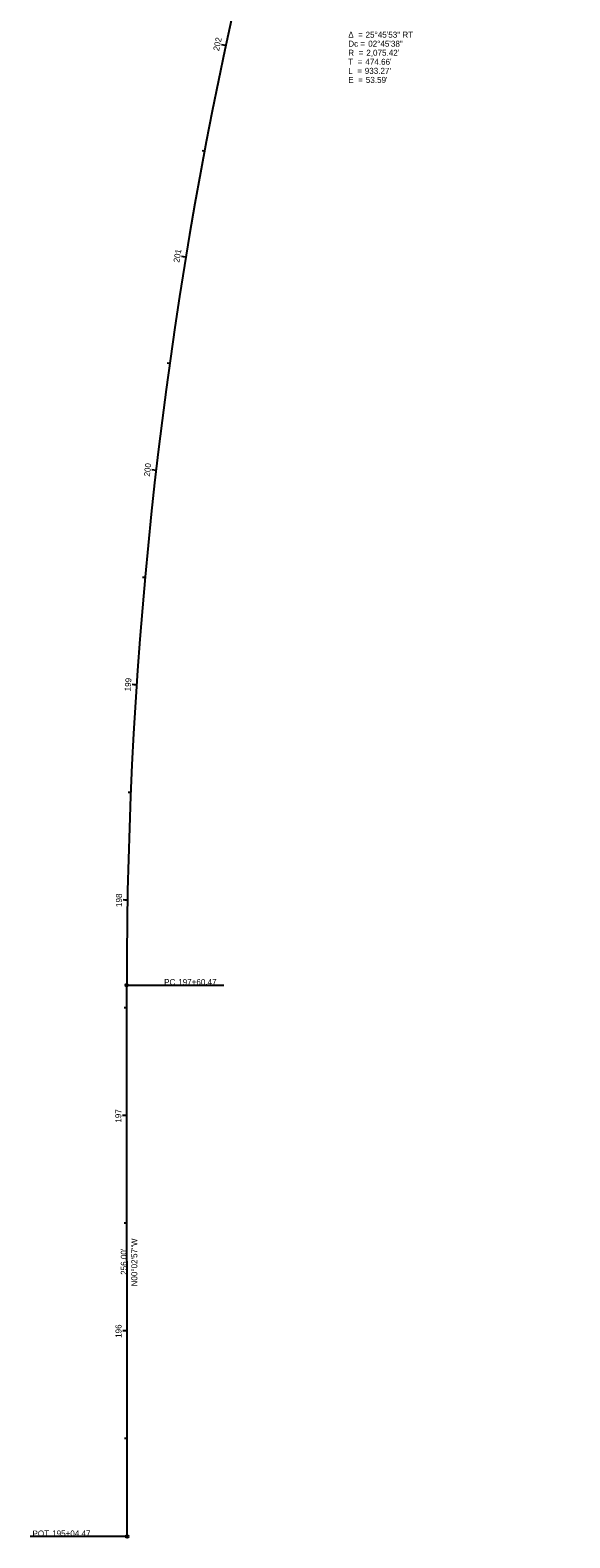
# Model space of a CAD drawing. Extents: x 1564507 to 1565178, y 635740 to 637470.
# Drawn here: x 1564742 to 1564993, y 635740 to 636440 of the extents above; entities that cross this region are included whole.
import ezdxf

# ---------------------------------------------------------------- set-up
doc = ezdxf.new("R2010")
doc.units = 0
for name, color, linetype in [('_CIVIL_CONSTRUCTION', 7, 'Continuous'), ('PM_P_CL_Double_Solid', 7, 'Continuous'), ('PM_P_Edge_Line', 7, 'Continuous'), ('PV_P_EOP', 7, 'Continuous'), ('PV_P_Shoulder', 7, 'Continuous'), ('RD_P_Wall', 7, 'Continuous'), ('RW_P_Const_Limits', 7, 'Continuous'), ('SC_Scratch1', 7, 'Continuous'), ('SC_Scratch2', 7, 'Continuous'), ('SC_Shading1', 7, 'Continuous'), ('SC_Shading3', 7, 'Continuous'), ('TR_Turning_Path2', 7, 'Continuous'), ('TR_Turning_Path5', 7, 'Continuous'), ('TR_Turning_Path6', 7, 'Continuous'), ('VG_P_Landscape_Limits', 7, 'Continuous')]:
    doc.layers.add(name, color=color, linetype=linetype)

msp = doc.modelspace()

# ---------------------------------------------------------------- linework, layer by layer
at = {"layer": '_CIVIL_CONSTRUCTION'}
msp.add_line((1564800.84, 636235.64), (1564798.85, 636235.87), dxfattribs=at)
at = {"layer": 'PM_P_CL_Double_Solid'}
for p, q in [((1564833.23, 636432.92), (1564831.27, 636433.34)), ((1564823.35, 636383.91), (1564822.17, 636384.13)), ((1564814.66, 636334.67), (1564812.68, 636335)), ((1564807.15, 636285.24), (1564805.96, 636285.41)), ((1564800.84, 636235.64), (1564798.85, 636235.87)), ((1564795.72, 636185.91), (1564794.53, 636186.02)), ((1564791.8, 636136.06), (1564789.81, 636136.19)), ((1564789.09, 636086.14), (1564787.89, 636086.19)), ((1564787.58, 636036.16), (1564785.58, 636036.2)), ((1564787.24, 635986.16), (1564786.04, 635986.16)), ((1564787.29, 635936.16), (1564785.29, 635936.16)), ((1564787.33, 635886.16), (1564786.13, 635886.16)), ((1564787.37, 635836.16), (1564785.37, 635836.16)), ((1564787.42, 635786.16), (1564786.22, 635786.16))]:
    msp.add_line(p, q, dxfattribs=at)
at = {"layer": 'PV_P_EOP'}
for p, q in [((1564787.24, 635996.63), (1564832.24, 635996.67)), ((1564787.45, 635740.63), (1564742.45, 635740.59))]:
    msp.add_line(p, q, dxfattribs=at)
for centre in [(1564787.24, 635996.63), (1564787.45, 635740.63)]:
    msp.add_circle(centre, 0.6, dxfattribs=at)
at = {"layer": 'PV_P_Shoulder'}
for p, q in [((1564787.24, 635996.63), (1564832.24, 635996.67)), ((1564787.45, 635740.63), (1564742.45, 635740.59))]:
    msp.add_line(p, q, dxfattribs=at)
for centre in [(1564787.24, 635996.63), (1564787.45, 635740.63)]:
    msp.add_circle(centre, 0.6, dxfattribs=at)
at = {"layer": 'SC_Scratch2'}
for p, q in [((1564833.23, 636432.92), (1564832.06, 636433.18)), ((1564814.66, 636334.67), (1564813.47, 636334.87)), ((1564800.84, 636235.64), (1564798.85, 636235.87)), ((1564791.8, 636136.06), (1564790.61, 636136.14)), ((1564787.58, 636036.16), (1564786.38, 636036.18)), ((1564787.29, 635936.16), (1564786.09, 635936.16)), ((1564787.37, 635836.16), (1564786.17, 635836.16))]:
    msp.add_line(p, q, dxfattribs=at)
at = {"layer": 'SC_Shading3'}
for p, q in [((1564787.24, 635996.63), (1564832.24, 635996.67)), ((1564787.45, 635740.63), (1564742.45, 635740.59))]:
    msp.add_line(p, q, dxfattribs=at)
for centre in [(1564787.24, 635996.63), (1564787.45, 635740.63)]:
    msp.add_circle(centre, 0.6, dxfattribs=at)
at = {"layer": 'TR_Turning_Path2'}
msp.add_line((1564787.45, 635740.63), (1564787.24, 635996.63), dxfattribs=at)
msp.add_line((1564787.45, 635740.63), (1564787.24, 635996.63), dxfattribs=at)
msp.add_arc((1566862.66, 635998.41), 2075.42, 154.28444, 180.04915, dxfattribs=at)
msp.add_arc((1566862.66, 635998.41), 2075.42, 154.28444, 180.04915, dxfattribs=at)

# ---------------------------------------------------------------- texts
at = {"layer": '_CIVIL_CONSTRUCTION'}
msp.add_text('200', height=2.8, rotation=83.43646, dxfattribs=at).set_placement((1564797.93, 636232.68))
at = {"layer": 'PM_P_CL_Double_Solid'}
for s, rotation, p in [('202', 77.91509, (1564830.05, 636430.26)), ('201', 80.67578, (1564811.64, 636332.02)), ('200', 83.43646, (1564797.93, 636232.68)), ('199', 86.19714, (1564789.05, 636132.99)), ('198', 88.95782, (1564784.97, 636032.93)), ('197', 90.04915, (1564784.74, 635932.82)), ('196', 90.04915, (1564784.83, 635832.88))]:
    msp.add_text(s, height=2.8, rotation=rotation, dxfattribs=at).set_placement(p)
at = {"layer": 'PM_P_Edge_Line'}
msp.add_text('N00°02\'57"W', height=2.8, rotation=90.04915, dxfattribs=at).set_placement((1564792.16, 635856.77))
at = {"layer": 'PV_P_EOP'}
for s, p in [('PC', (1564804.6, 635996.69)), ('197+60.47', (1564811.12, 635996.7)), ('POT', (1564743.52, 635740.64)), ('195+04.47', (1564752.65, 635740.65))]:
    msp.add_text(s, height=2.8, rotation=0.04915, dxfattribs=at).set_placement(p)
at = {"layer": 'PV_P_Shoulder'}
for s, p in [('PC', (1564804.6, 635996.69)), ('197+60.47', (1564811.12, 635996.7)), ('POT', (1564743.52, 635740.64)), ('195+04.47', (1564752.65, 635740.65))]:
    msp.add_text(s, height=2.8, rotation=0.04915, dxfattribs=at).set_placement(p)
at = {"layer": 'RD_P_Wall'}
msp.add_text("256.00'", height=2.8, rotation=90.04915, dxfattribs=at).set_placement((1564787.3, 635862.15))
at = {"layer": 'RW_P_Const_Limits'}
msp.add_text("256.00'", height=2.8, rotation=90.04915, dxfattribs=at).set_placement((1564787.3, 635862.15))
at = {"layer": 'SC_Scratch1'}
msp.add_text("256.00'", height=2.8, rotation=90.04915, dxfattribs=at).set_placement((1564787.3, 635862.15))
at = {"layer": 'SC_Scratch2'}
msp.add_text('200', height=2.8, rotation=83.43646, dxfattribs=at).set_placement((1564797.93, 636232.68))
at = {"layer": 'SC_Shading1'}
msp.add_text('N00°02\'57"W', height=2.8, rotation=90.04915, dxfattribs=at).set_placement((1564792.16, 635856.77))
at = {"layer": 'SC_Shading3'}
for s, p in [('PC', (1564804.6, 635996.69)), ('197+60.47', (1564811.12, 635996.7)), ('POT', (1564743.52, 635740.64)), ('195+04.47', (1564752.65, 635740.65))]:
    msp.add_text(s, height=2.8, rotation=0.04915, dxfattribs=at).set_placement(p)
at = {"layer": 'TR_Turning_Path5'}
msp.add_text('N00°02\'57"W', height=2.8, rotation=90.04915, dxfattribs=at).set_placement((1564792.16, 635856.77))
at = {"layer": 'TR_Turning_Path6'}
for s, p in [('Δ  = ', (1564890.01, 636436.59)), ('25°45\'53" RT', (1564898.03, 636436.59)), ('Dc = ', (1564890.01, 636432.39)), ('R  = ', (1564890.01, 636428.19)), ("2,075.42'", (1564898.38, 636428.19)), ('02°45\'38"', (1564899.25, 636432.39)), ('T  = ', (1564890.01, 636423.99)), ("474.66'", (1564897.94, 636423.99)), ('L  = ', (1564890.01, 636419.79)), ('E  = ', (1564890.01, 636415.59)), ("933.27'", (1564897.66, 636419.79)), ("53.59'", (1564898.16, 636415.59))]:
    msp.add_text(s, height=2.8, dxfattribs=at).set_placement(p)
at = {"layer": 'VG_P_Landscape_Limits'}
for s, p in [('Δ  = ', (1564890.01, 636436.59)), ('25°45\'53" RT', (1564898.03, 636436.59)), ('Dc = ', (1564890.01, 636432.39)), ('R  = ', (1564890.01, 636428.19)), ("2,075.42'", (1564898.38, 636428.19)), ('02°45\'38"', (1564899.25, 636432.39)), ('T  = ', (1564890.01, 636423.99)), ("474.66'", (1564897.94, 636423.99)), ('L  = ', (1564890.01, 636419.79)), ('E  = ', (1564890.01, 636415.59)), ("933.27'", (1564897.66, 636419.79)), ("53.59'", (1564898.16, 636415.59))]:
    msp.add_text(s, height=2.8, dxfattribs=at).set_placement(p)

doc.saveas('drawing.dxf')
